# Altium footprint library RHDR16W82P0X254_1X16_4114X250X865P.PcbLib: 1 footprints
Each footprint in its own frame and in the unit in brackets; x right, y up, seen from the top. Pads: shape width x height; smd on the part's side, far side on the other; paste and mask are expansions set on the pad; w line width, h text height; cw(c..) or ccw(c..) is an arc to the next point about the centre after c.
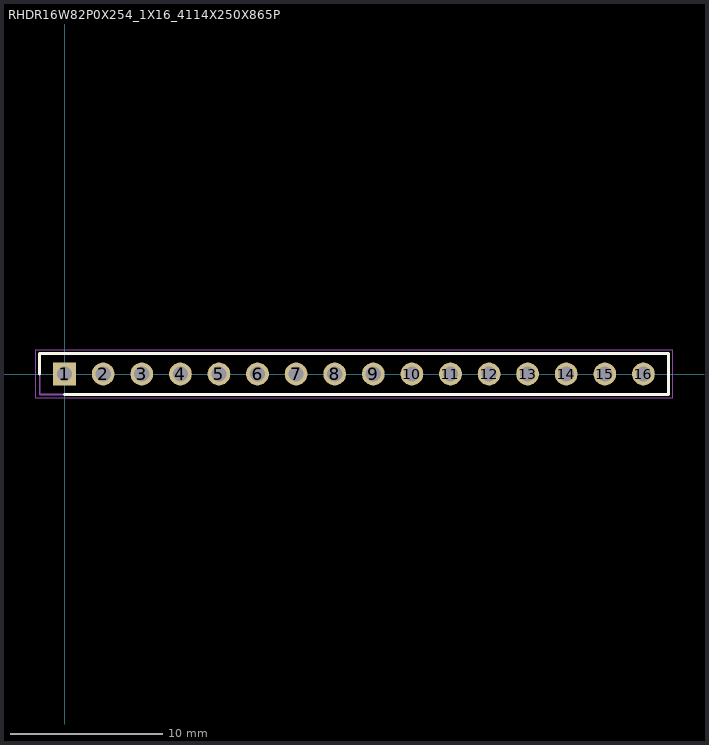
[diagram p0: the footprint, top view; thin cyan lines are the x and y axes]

## RHDR16W82P0X254_1X16_4114X250X865P [mm]
pads (16):
  rect 1.5x1.5 / inner round 1.5 / far side rect 1.5x1.5 hole 1: 1(0,0)
  round 1.5 hole 1: 2(2.54,0) 3(5.08,0) 4(7.62,0) 5(10.16,0) 6(12.7,0) 7(15.24,0) 8(17.78,0) 9(20.32,0) 10(22.86,0) 11(25.4,0) 12(27.94,0) 13(30.48,0) 14(33.02,0) 15(35.56,0) 16(38.1,0)
Top Overlay:
  lines w0.2: -1.645,0 -1.645,1.35 39.745,1.35 39.745,-1.35 0,-1.35
Mechanical 15:
  lines w0.1: -1.645,-1.35 -1.645,1.35 39.745,1.35 39.745,-1.35 -1.645,-1.35
Mechanical 20:
  lines w0.05: -1.895,-1.6 -1.895,1.6 39.995,1.6 39.995,-1.6 -1.895,-1.6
